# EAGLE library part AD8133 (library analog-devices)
Triple Differential Driver With Output Pull-Down Source: http://www.analog.com .. 3832984220209AD8133_0.pdf
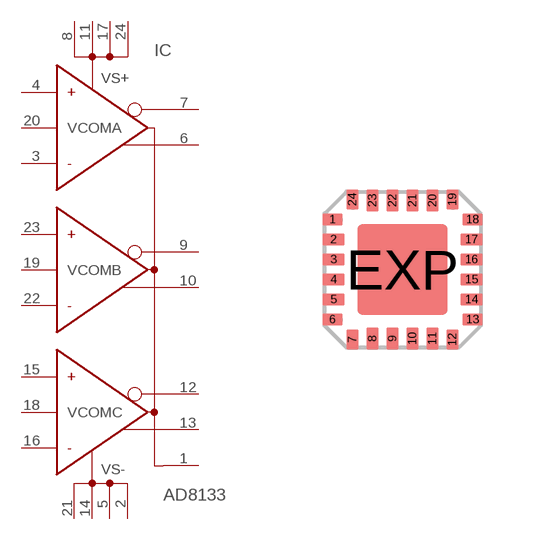
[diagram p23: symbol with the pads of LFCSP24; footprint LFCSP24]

Designator prefix IC

## AD8133 (MF: ALTERA CORPORATION; MPN: AD8133ACPZ-REEL7; OC_FARNELL: unknown; OC_NEWARK: 59K6409)  [LFCSP24]
1  OPD  in
2  VS-  pwr
3  -INA  in
4  +INA  in
5  VS-  pwr
6  -OUTA  out
7  +OUTA  out
8  VS+  pwr
9  +OUTB  out
10  -OUTB  out
11  VS+  pwr
12  +OUTC  out
13  -OUTC  out
14  VS-  pwr
15  +INC  in
16  -INC  in
17  VS+  pwr
18  VCOMC  in
19  VCOMB  in
20  VCOMA  in
21  VS-  pwr
22  -INB  in
23  +INB  in
24  VS+  pwr

## Footprint LFCSP24 (pad centres in mm)
24-Lead Lead Frame Chip Scale Package 4 mm × 4 mm (CP-24) Source: www.analog.com .. 3832984220209AD8133_0.pdf
smd 0.5 x 0.3: 1 -1.75,1.25; 6 -1.75,-1.25; 13 1.75,-1.25; 18 1.75,1.25
smd 0.55 x 0.3: 2 -1.725,0.75; 3 -1.725,0.25; 4 -1.725,-0.25; 5 -1.725,-0.75; 14 1.725,-0.75; 15 1.725,-0.25; 16 1.725,0.25; 17 1.725,0.75
smd 0.3 x 0.5: 7 -1.25,-1.75; 12 1.25,-1.75; 19 1.25,1.75; 24 -1.25,1.75
smd 0.3 x 0.55: 8 -0.75,-1.725; 9 -0.25,-1.725; 10 0.25,-1.725; 11 0.75,-1.725; 20 0.75,1.725; 21 0.25,1.725; 22 -0.25,1.725; 23 -0.75,1.725
smd 2.25 x 2.25: EXP 0,0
